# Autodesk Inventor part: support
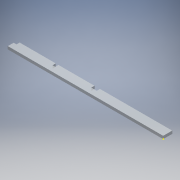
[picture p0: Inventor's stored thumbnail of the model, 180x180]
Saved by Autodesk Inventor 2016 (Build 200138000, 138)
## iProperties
Created: 2015-11
Part Number: support
Material: Generic
Document SubType Name: Modeling
Designer: t_silvdo
Density: 1 g/cm^3
Appearance: Default
Author: t_silvdo
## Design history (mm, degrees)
sketch "Sketch1"
  geometry: 1 further point
sketch "Sketch2"
  geometry: L1 (0, 0)-(0, -9.525); L2 (0, -9.525)-(76.2, -9.525); L3 (76.2, -9.525)-(76.2, -6.144); L4 (76.2, -6.144)-(81.946, -6.144); L5 (81.946, -6.144)-(81.946, -9.525); L6 (81.946, -9.525)-(120.046, -9.525); L7 (120.046, -9.525)-(120.046, -6.144); L8 (120.046, -6.144)-(122.792, -6.144); L9 (122.792, -6.144)-(122.792, -9.525); L10 (122.792, -9.525)-(160.892, -9.525); L11 (160.892, -9.525)-(160.892, -6.144); L12 (160.892, -6.144)-(163.892, -6.144); L13 (0, 0)-(163.892, 0); L14 (163.892, 0)-(163.892, -6.144)
  constraints: 28 end point, 9 perpendicular, 5 point on line, 2 horizontal, 1 vertical
  dimensions: "d0" = 9.525 distance of L1.start L1.end; "d1" = 76.2 distance of L1.end L2.end; "d2" = 3.381 distance of L2.end L3.end (= acrylic + t); "d3" = 5.746 distance of L3.end L4.end (= xray + 2 x acrylic - t); "d4" = 38.1 distance of L5.end L6.end; "d5" = 3.381 distance of L6.end L7.end (= acrylic + t); "d6" = 2.746 distance of L7.end L8.end (computed from acrylic); "d7" = 38.1 distance of L9.end L10.end; "d8" = 3 distance of L11.end L12.end (= acrylic); "d11" = 163.892 distance of L1.start L13.end (derived)
extrude "Extrusion1" new body sketch "Sketch2" distance "d9" = 3 (= acrylic); taper "d10" = 0 deg
body "Solid1"
other parameters: "acrylic" = 3 [user parameter; used in 6 equation terms], "t" = 0.381 [user parameter; used in 3 equation terms], "box_height" = 163.6268 [user parameter], "xray" = 0.127 [user parameter; used in 1 equation term]
